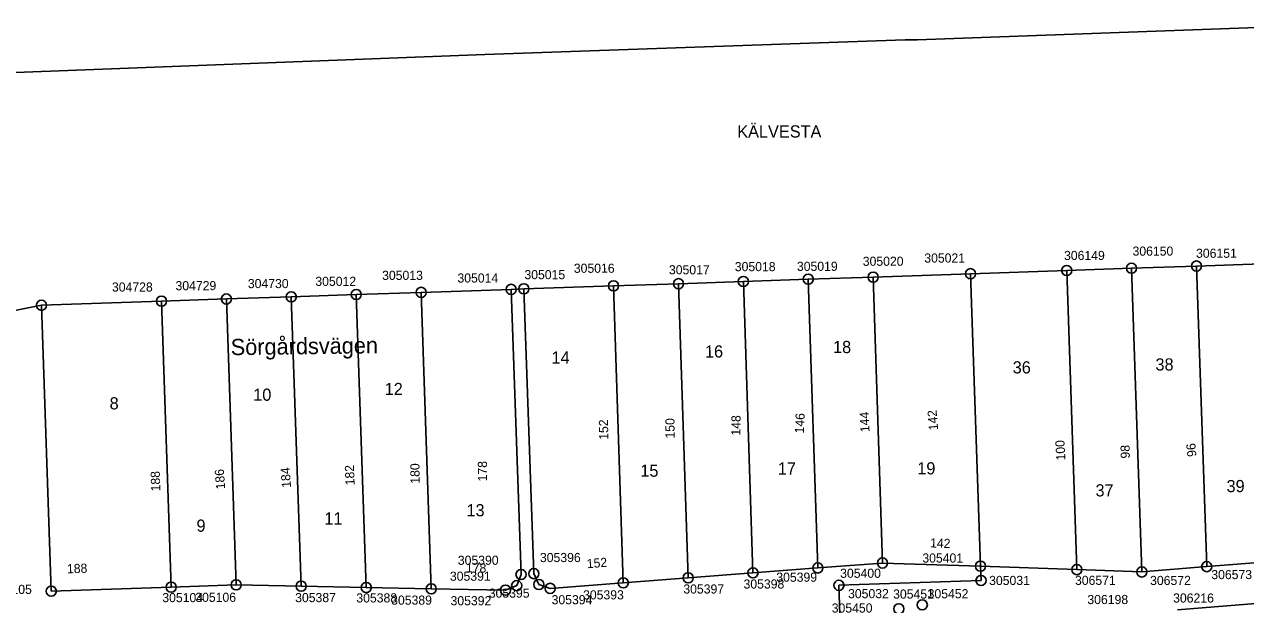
# Model space of a CAD drawing. Extents: x 141995 to 152570, y 6580184 to 6586000.
# Drawn here: x 142125.3 to 142245.6, y 6585289.1 to 6585346.3 of the extents above; entities that cross this region are included whole.
import ezdxf

# ---------------------------------------------------------------- set-up
doc = ezdxf.new("R2010")
doc.units = 0
for name, color, linetype in [('Level 10', 7, 'Continuous'), ('Level 13', 7, 'Continuous'), ('Level 43', 7, 'Continuous'), ('Level 5', 7, 'Continuous'), ('Level 51', 7, 'Continuous'), ('Level 53', 7, 'Continuous'), ('Level 54', 7, 'Continuous'), ('Level 55', 7, 'Continuous'), ('Level 56', 7, 'Continuous'), ('Level 6', 7, 'Continuous'), ('Level 7', 7, 'Continuous')]:
    doc.layers.add(name, color=color, linetype=linetype)

msp = doc.modelspace()

# ---------------------------------------------------------------- linework, layer by layer
at = {"layer": 'Level 10'}
for centre in [(142208.96, 6585321.37), (142218.55, 6585321.7), (142228.02, 6585322.02), (142234.41, 6585322.24), (142240.81, 6585322.46), (142173.29, 6585320.16), (142174.54, 6585320.21), (142183.37, 6585320.51), (142189.77, 6585320.72), (142196.16, 6585320.94), (142202.56, 6585321.16), (142138.83, 6585318.99), (142145.22, 6585319.21), (142151.62, 6585319.43), (142158.02, 6585319.65), (142164.41, 6585319.86), (142127.01, 6585318.59), (142203.5, 6585292.7), (142209.88, 6585293.19), (142219.53, 6585292.87), (142229.02, 6585292.54), (142241.82, 6585292.83), (142174.26, 6585292.06), (142175.51, 6585292.14), (142190.72, 6585291.73), (142197.11, 6585292.22), (142219.58, 6585291.47), (142235.43, 6585292.31), (142127.97, 6585290.41), (142139.79, 6585290.81), (142146.19, 6585291.03), (142152.6, 6585290.9), (142159.01, 6585290.78), (142165.41, 6585290.65), (142172.73, 6585290.51), (142173.83, 6585290.96), (142176.01, 6585291.07), (142177.12, 6585290.69), (142184.33, 6585291.24), (142205.58, 6585290.99), (142213.79, 6585289.06), (142211.49, 6585288.67)]:
    msp.add_circle(centre, 0.5, dxfattribs=at)
at = {"layer": 'Level 13'}
for points in [[(142219.63, 6585344.99), (142254.95, 6585346.27)], [(142170.68, 6585343.31), (142212.12, 6585344.75)], [(142212.12, 6585344.75), (142213.33, 6585344.76)], [(142213.33, 6585344.76), (142219.63, 6585344.99)], [(142096.17, 6585340.46), (142170.68, 6585343.31)]]:
    msp.add_lwpolyline(points, dxfattribs=at)
at = {"layer": 'Level 5'}
for points in [[(142218.55, 6585321.7), (142228.02, 6585322.02)], [(142228.02, 6585322.02), (142234.41, 6585322.24)], [(142234.41, 6585322.24), (142240.81, 6585322.46)], [(142240.81, 6585322.46), (142247.21, 6585322.67)], [(142183.37, 6585320.51), (142189.77, 6585320.72)], [(142189.77, 6585320.72), (142196.16, 6585320.94)], [(142196.16, 6585320.94), (142202.56, 6585321.16)], [(142202.56, 6585321.16), (142208.96, 6585321.37)], [(142208.96, 6585321.37), (142218.55, 6585321.7)], [(142151.62, 6585319.43), (142158.02, 6585319.65)], [(142158.02, 6585319.65), (142164.41, 6585319.86)], [(142164.41, 6585319.86), (142173.29, 6585320.16)], [(142173.29, 6585320.16), (142174.54, 6585320.21)], [(142174.54, 6585320.21), (142183.37, 6585320.51)], [(142098.85, 6585313), (142127.01, 6585318.59)], [(142127.01, 6585318.59), (142138.83, 6585318.99)], [(142138.83, 6585318.99), (142145.22, 6585319.21)], [(142145.22, 6585319.21), (142151.62, 6585319.43)]]:
    msp.add_lwpolyline(points, dxfattribs=at)
at = {"layer": 'Level 6'}
for points in [[(142247.21, 6585322.67), (142240.81, 6585322.46), (142234.41, 6585322.24), (142228.02, 6585322.02), (142218.55, 6585321.7), (142208.96, 6585321.37), (142202.56, 6585321.16)], [(142202.56, 6585321.16), (142196.16, 6585320.94), (142189.77, 6585320.72), (142183.37, 6585320.51), (142174.54, 6585320.21), (142173.29, 6585320.16), (142164.41, 6585319.86), (142158.02, 6585319.65), (142151.62, 6585319.43), (142145.22, 6585319.21), (142138.83, 6585318.99), (142127.01, 6585318.59), (142098.85, 6585313)]]:
    msp.add_lwpolyline(points, dxfattribs=at)
at = {"layer": 'Level 7'}
for points in [[(142228.02, 6585322.02), (142229.02, 6585292.54)], [(142234.41, 6585322.24), (142235.43, 6585292.31)], [(142240.81, 6585322.46), (142241.82, 6585292.83)], [(142189.77, 6585320.72), (142190.72, 6585291.73)], [(142196.16, 6585320.94), (142197.11, 6585292.22)], [(142202.56, 6585321.16), (142203.5, 6585292.7)], [(142208.96, 6585321.37), (142209.88, 6585293.19)], [(142218.55, 6585321.7), (142219.53, 6585292.87)], [(142158.02, 6585319.65), (142159.01, 6585290.78)], [(142164.41, 6585319.86), (142165.41, 6585290.65)], [(142173.29, 6585320.16), (142174.26, 6585292.06)], [(142175.51, 6585292.14), (142174.54, 6585320.21)], [(142183.37, 6585320.51), (142184.33, 6585291.24)], [(142127.97, 6585290.41), (142127.01, 6585318.59)], [(142138.83, 6585318.99), (142139.79, 6585290.81)], [(142145.22, 6585319.21), (142146.19, 6585291.03)], [(142151.62, 6585319.43), (142152.6, 6585290.9)], [(142209.88, 6585293.19), (142203.5, 6585292.7)], [(142219.53, 6585292.87), (142209.88, 6585293.19)], [(142241.82, 6585292.83), (142248.21, 6585293.34)], [(142174.26, 6585292.06), (142173.83, 6585290.96)], [(142176.01, 6585291.07), (142175.51, 6585292.14)], [(142197.11, 6585292.22), (142190.72, 6585291.73)], [(142203.5, 6585292.7), (142197.11, 6585292.22)], [(142219.58, 6585291.47), (142219.53, 6585292.87)], [(142219.53, 6585292.87), (142229.02, 6585292.54)], [(142229.02, 6585292.54), (142235.43, 6585292.31)], [(142235.43, 6585292.31), (142241.82, 6585292.83)], [(142139.79, 6585290.81), (142127.97, 6585290.41)], [(142146.19, 6585291.03), (142139.79, 6585290.81)], [(142152.6, 6585290.9), (142146.19, 6585291.03)], [(142159.01, 6585290.78), (142152.6, 6585290.9)], [(142165.41, 6585290.65), (142159.01, 6585290.78)], [(142172.73, 6585290.51), (142165.41, 6585290.65)], [(142173.83, 6585290.96), (142172.73, 6585290.51)], [(142177.12, 6585290.69), (142176.01, 6585291.07)], [(142184.33, 6585291.24), (142177.12, 6585290.69)], [(142190.72, 6585291.73), (142184.33, 6585291.24)], [(142205.58, 6585290.99), (142219.58, 6585291.47)], [(142206.5, 6585264.14), (142205.58, 6585290.99)], [(142238.94, 6585288.58), (142260.02, 6585290.29)]]:
    msp.add_lwpolyline(points, dxfattribs=at)

# ---------------------------------------------------------------- texts
at = {"layer": 'Level 43'}
msp.add_text('Sörgårdsvägen', height=1.6, rotation=0.7346, dxfattribs=at).set_placement((142145.66, 6585313.67))
at = {"layer": 'Level 51'}
for s, p in [('16', (142192.38, 6585313.44)), ('18', (142205, 6585313.88)), ('14', (142177.26, 6585312.84)), ('36', (142222.7, 6585311.87)), ('38', (142236.77, 6585312.16)), ('10', (142147.87, 6585309.18)), ('12', (142160.82, 6585309.74)), ('8', (142133.72, 6585308.33)), ('15', (142186.01, 6585301.69)), ('17', (142199.56, 6585301.91)), ('19', (142213.3, 6585301.92)), ('39', (142243.77, 6585300.17)), ('37', (142230.86, 6585299.75)), ('13', (142168.88, 6585297.79)), ('11', (142154.88, 6585296.98)), ('9', (142142.28, 6585296.27))]:
    msp.add_text(s, height=1.2, rotation=0.0526, dxfattribs=at).set_placement(p)
at = {"layer": 'Level 53'}
for s, p in [('306150', (142234.51, 6585323.48)), ('305020', (142207.93, 6585322.48)), ('305021', (142213.99, 6585322.8)), ('306149', (142227.76, 6585323.05)), ('306151', (142240.77, 6585323.27)), ('305013', (142160.57, 6585321.09)), ('305015', (142174.59, 6585321.16)), ('305016', (142179.46, 6585321.79)), ('305017', (142188.83, 6585321.64)), ('305018', (142195.32, 6585321.95)), ('305019', (142201.44, 6585321.98)), ('304728', (142133.95, 6585319.94)), ('304729', (142140.21, 6585320.07)), ('304730', (142147.34, 6585320.28)), ('305012', (142153.99, 6585320.5)), ('305014', (142167.99, 6585320.83)), ('305396', (142176.12, 6585293.28)), ('305390', (142168.03, 6585293.01)), ('305401', (142213.8, 6585293.23)), ('305391', (142167.25, 6585291.44)), ('305399', (142199.41, 6585291.34)), ('305400', (142205.7, 6585291.73)), ('305031', (142220.38, 6585291.02)), ('306571', (142228.84, 6585291.03)), ('306572', (142236.24, 6585291.02)), ('306573', (142242.27, 6585291.6)), ('305105', (142122.04, 6585290.14)), ('305395', (142171.08, 6585289.77)), ('305397', (142190.25, 6585290.18)), ('305398', (142196.18, 6585290.67)), ('305032', (142206.48, 6585289.72)), ('305451', (142210.92, 6585289.68)), ('305452', (142214.32, 6585289.71)), ('305104', (142138.91, 6585289.33)), ('305106', (142142.16, 6585289.36)), ('305387', (142152, 6585289.33)), ('305388', (142158.03, 6585289.3)), ('305389', (142161.46, 6585289.08)), ('305392', (142167.31, 6585289.02)), ('305394', (142177.27, 6585289.12)), ('305393', (142180.37, 6585289.6)), ('306198', (142230.06, 6585289.14)), ('306216', (142238.51, 6585289.29)), ('305450', (142204.87, 6585288.3))]:
    msp.add_text(s, height=0.9, rotation=0.0526, dxfattribs=at).set_placement(p)
at = {"layer": 'Level 54'}
for s, rotation, p in [('150', 90.4017, (142189.39, 6585305.46)), ('148', 89.4027, (142195.87, 6585305.74)), ('146', 87.2346, (142202.12, 6585305.94)), ('144', 92.5278, (142208.6, 6585306.1)), ('142', 94.8598, (142215.36, 6585306.3)), ('152', 91.0437, (142182.86, 6585305.34)), ('100', 93.1398, (142227.9, 6585303.32)), ('98', 90.5667, (142234.24, 6585303.49)), ('96', 95.8859, (142240.82, 6585303.7)), ('184', 94.2588, (142151.6, 6585300.64)), ('182', 91.9807, (142157.86, 6585300.86)), ('180', 90.3527, (142164.26, 6585301.01)), ('178', 90.7637, (142170.92, 6585301.24)), ('188', 91.9807, (142138.72, 6585300.26)), ('186', 94.2588, (142145.11, 6585300.48))]:
    msp.add_text(s, height=0.9, rotation=rotation, dxfattribs=at).set_placement(p)
at = {"layer": 'Level 55'}
for s, rotation, p in [('142', 358.0816, (142214.55, 6585294.73)), ('188', 1.9365, (142129.53, 6585292.17)), ('178', 358.8786, (142168.82, 6585292.28)), ('152', 4.3645, (142180.77, 6585292.67))]:
    msp.add_text(s, height=0.9, rotation=rotation, dxfattribs=at).set_placement(p)
at = {"layer": 'Level 56'}
msp.add_text('KÄLVESTA', height=1.2, rotation=0.0526, dxfattribs=at).set_placement((142195.56, 6585335.12))

doc.saveas('drawing.dxf')
